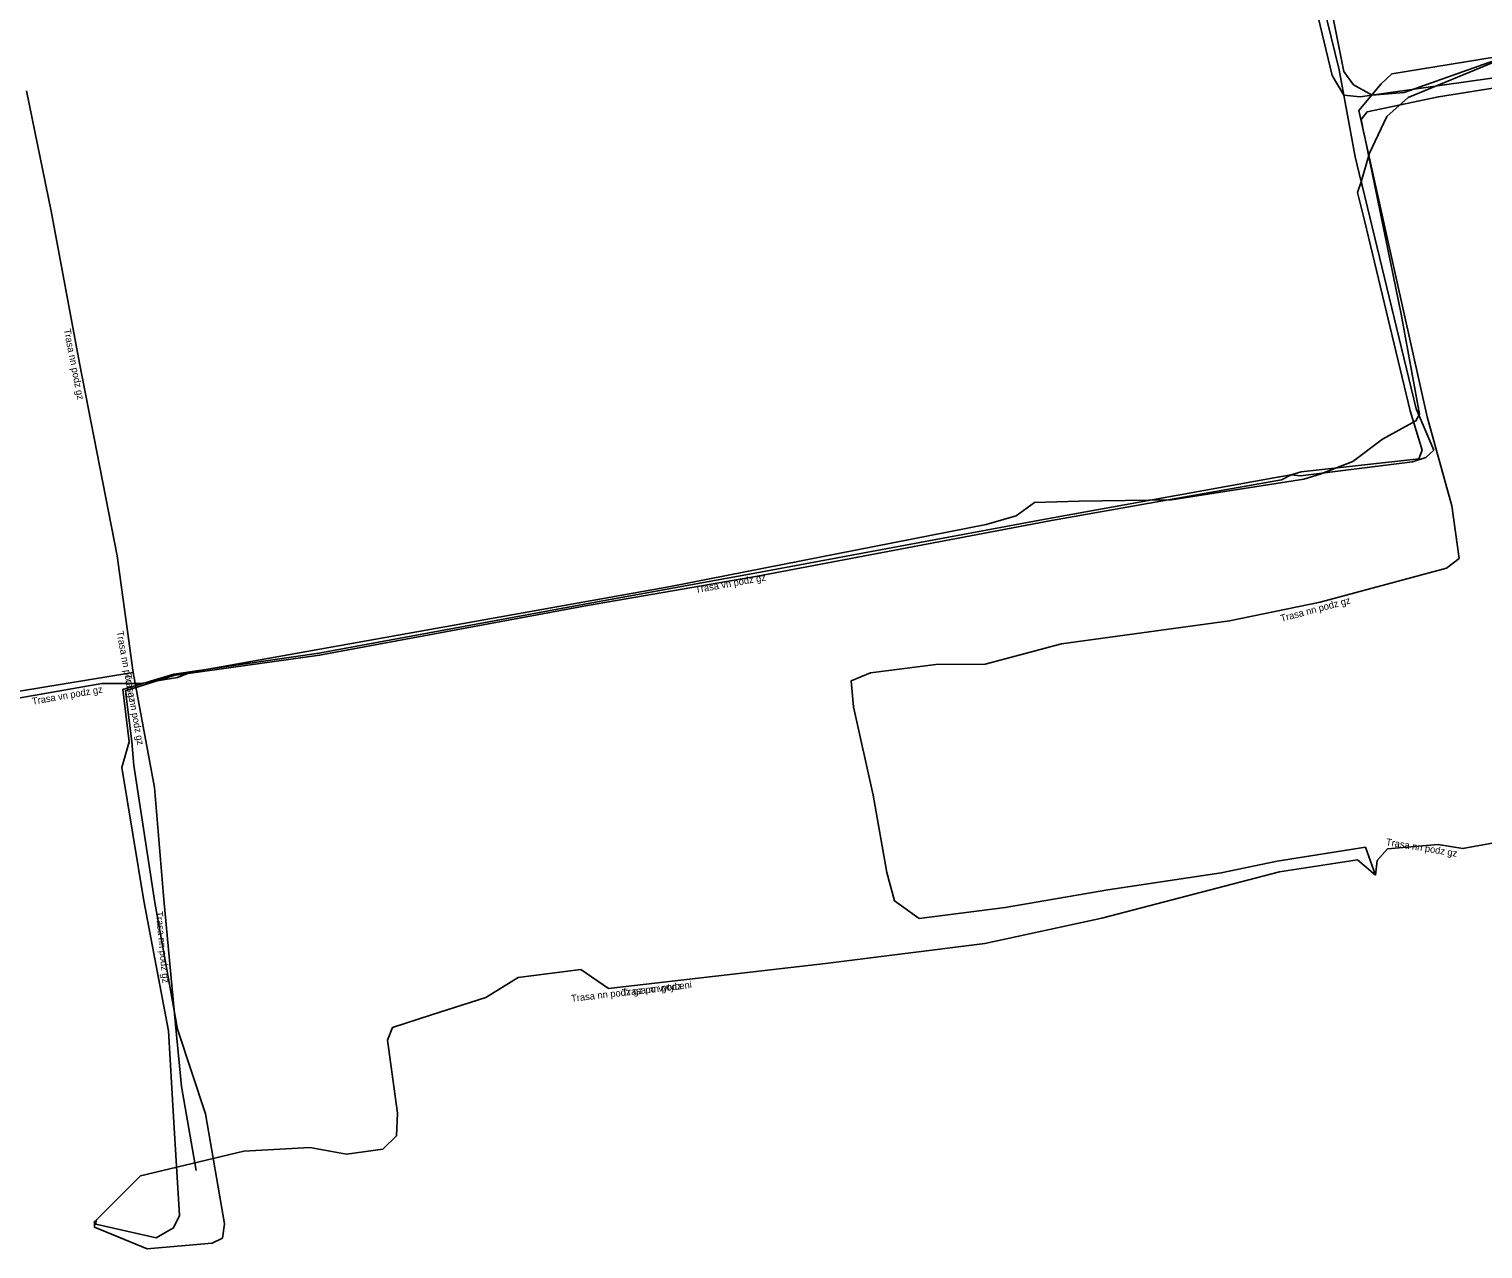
# Model space of a CAD drawing. Extents: x -473082 to -472599, y -1107914 to -1107370.
# Drawn here: x -472981 to -472876.8, y -1107720.1 to -1107632.7 of the extents above; entities that cross this region are included whole.
import ezdxf

# ---------------------------------------------------------------- set-up
doc = ezdxf.new("R2010")
doc.units = 0
for name, color, linetype in [('Popiskový text - Ostatní atributy Trasy', 7, 'Continuous'), ('Spojnice NN', 7, 'Continuous'), ('Spojnice VN', 7, 'Continuous')]:
    doc.layers.add(name, color=color, linetype=linetype)

msp = doc.modelspace()

# ---------------------------------------------------------------- linework, layer by layer
at = {"layer": 'Spojnice NN'}
for points in [[(-472875.97, -1107634.7), (-472883.29, -1107635.91), (-472884.07, -1107636.61), (-472885.67, -1107638.54), (-472883.02, -1107650.42), (-472880.76, -1107660.48), (-472879, -1107666.86), (-472878.47, -1107670.62), (-472879.39, -1107671.32), (-472888.44, -1107673.75), (-472894.93, -1107675.1), (-472906.98, -1107676.74), (-472912.44, -1107678.19), (-472915.97, -1107678.23), (-472920.65, -1107678.82), (-472922.05, -1107679.39), (-472921.88, -1107681.26), (-472920.47, -1107687.59), (-472919.49, -1107693.13), (-472918.93, -1107695.15), (-472917.16, -1107696.42), (-472911, -1107695.63), (-472903.64, -1107694.35), (-472895.52, -1107693.15), (-472891.51, -1107692.3), (-472885.2, -1107691.31), (-472884.48, -1107693.31)], [(-472981.13, -1107637.11), (-472979.37, -1107645.75), (-472977.34, -1107656.62), (-472974.63, -1107670.44), (-472973.49, -1107678.79)], [(-472997.51, -1107676.91), (-472996.73, -1107681.91), (-472995.7, -1107682.72), (-472990.89, -1107681.76), (-472981.63, -1107680.12), (-472973.49, -1107678.79)], [(-472973.49, -1107678.79), (-472973.2, -1107680.34)], [(-472973.2, -1107680.34), (-472972.35, -1107684.97)], [(-472972.35, -1107684.97), (-472971.97, -1107687.02), (-472971.3, -1107695.06), (-472970.46, -1107704), (-472970.02, -1107708.44), (-472968.98, -1107714.47)], [(-472873.9, -1107690.6), (-472878.21, -1107691.41), (-472879.98, -1107691.12), (-472883.62, -1107691.43), (-472884.35, -1107692.25), (-472884.48, -1107693.31)], [(-472884.48, -1107693.31), (-472885.77, -1107692.21), (-472891.34, -1107693.08), (-472904.07, -1107696.4), (-472912.47, -1107698.21), (-472923.89, -1107699.63), (-472939.43, -1107701.43), (-472941.42, -1107700.06), (-472945.91, -1107700.65), (-472948.22, -1107702.07), (-472952.11, -1107703.31), (-472954.9, -1107704.22), (-472955.27, -1107705.14), (-472954.55, -1107710.36), (-472954.62, -1107711.99), (-472955.6, -1107712.94), (-472958.21, -1107713.29), (-472960.83, -1107712.83), (-472965.57, -1107713.09), (-472972.96, -1107714.86), (-472976.14, -1107718.03)], [(-472884.48, -1107693.31), (-472885.77, -1107692.21), (-472891.34, -1107693.08), (-472904.07, -1107696.4), (-472912.47, -1107698.21), (-472923.89, -1107699.63), (-472939.43, -1107701.43), (-472941.42, -1107700.06), (-472945.91, -1107700.65), (-472948.22, -1107702.07), (-472952.11, -1107703.31), (-472954.9, -1107704.22), (-472955.27, -1107705.14), (-472954.55, -1107710.36), (-472954.62, -1107711.99), (-472955.6, -1107712.94), (-472958.21, -1107713.29), (-472960.83, -1107712.83), (-472965.57, -1107713.09), (-472972.96, -1107714.86), (-472976.14, -1107718.03)]]:
    msp.add_lwpolyline(points, dxfattribs=at)
at = {"layer": 'Spojnice VN'}
for points in [[(-472875.95, -1107634.94), (-472882.42, -1107637.24), (-472884.7, -1107637.44), (-472886.06, -1107636.68), (-472886.73, -1107635.73), (-472888.17, -1107628.55), (-472889.42, -1107623.23), (-472890.17, -1107619.72), (-472891.75, -1107613.81), (-472894.87, -1107599.99), (-472897.4, -1107589.9), (-472899.37, -1107581.45), (-472900.86, -1107575.05), (-472901.22, -1107573.68), (-472903.13, -1107567.52), (-472905.32, -1107556.79), (-472907.67, -1107546.67)], [(-472872.74, -1107635.74), (-472879.7, -1107636.72), (-472885.57, -1107637.54), (-472886.75, -1107637.43), (-472887.57, -1107636.03), (-472890.88, -1107622.26), (-472896.66, -1107598.66), (-472901.17, -1107578.99), (-472901.72, -1107578.58), (-472904.16, -1107579.08), (-472907.72, -1107579.66), (-472913.35, -1107580.97), (-472931.82, -1107585.01), (-472935.78, -1107585.94), (-472940.39, -1107586.9), (-472941.18, -1107586.07), (-472941.89, -1107582.19), (-472945.77, -1107566.21), (-472946.59, -1107566.01), (-472951.81, -1107566.48), (-472951.81, -1107566.06), (-472951.68, -1107565.97)], [(-472976.14, -1107718.03), (-472976.14, -1107718.13), (-472976.18, -1107718.13), (-472976.18, -1107718.32), (-472971.84, -1107719.3), (-472970.6, -1107718.58), (-472970.17, -1107717.68), (-472970.6, -1107710.63), (-472970.95, -1107704.47), (-472972.74, -1107695.15), (-472974.3, -1107685.59), (-472973.78, -1107683.75), (-472974.24, -1107680.02), (-472970.59, -1107678.9), (-472960.18, -1107677.41), (-472941, -1107673.87), (-472928.43, -1107671.59), (-472907.88, -1107667.77), (-472891.34, -1107664.78), (-472890.52, -1107664.63), (-472889.85, -1107664.7), (-472881.81, -1107663.71), (-472880.87, -1107663.4), (-472880.3, -1107662.87), (-472881.55, -1107659.9), (-472885.4, -1107644), (-472885.49, -1107643.64), (-472885.94, -1107641.84), (-472887.07, -1107635.61), (-472888.78, -1107628.66)], [(-472976.14, -1107718.03), (-472976.16, -1107718.11), (-472976.27, -1107718.11), (-472976.27, -1107718.52), (-472972.5, -1107720.08), (-472971.97, -1107720.03), (-472967.84, -1107719.68), (-472967.1, -1107719.31), (-472966.94, -1107718.3), (-472968.32, -1107710.41), (-472970.31, -1107704.35), (-472971.95, -1107695.28), (-472973.44, -1107685.46), (-472973.6, -1107683.75), (-472974.05, -1107680.11), (-472970.57, -1107679.01), (-472960.14, -1107677.56), (-472940.94, -1107674), (-472928.76, -1107671.88), (-472907.7, -1107667.9), (-472891.21, -1107664.99), (-472890.52, -1107664.63), (-472889.81, -1107664.42), (-472881.37, -1107663.49), (-472881.12, -1107662.87), (-472881.98, -1107660.05), (-472885.27, -1107646.42), (-472885.75, -1107644.4), (-472885.49, -1107643.64), (-472884.91, -1107641.59), (-472883.65, -1107638.96), (-472882.14, -1107637.59), (-472875.46, -1107634.86)], [(-472885.28, -1107640.28), (-472885.49, -1107639.17), (-472885.07, -1107638.63), (-472879.96, -1107637.54), (-472859.98, -1107634.38)], [(-472885.28, -1107640.28), (-472885.27, -1107640.33), (-472882.64, -1107653.13), (-472881.31, -1107660.28), (-472881.57, -1107660.77), (-472883.97, -1107662.08), (-472886.1, -1107663.68), (-472888.44, -1107664.58), (-472889.6, -1107664.93), (-472899.08, -1107666.41), (-472905.7, -1107666.52), (-472908.91, -1107666.61), (-472910.21, -1107667.56), (-472912.36, -1107668.19), (-472935, -1107672.62), (-472969.33, -1107678.77), (-472970.32, -1107679.14), (-472972.94, -1107679.57), (-472975.73, -1107679.57), (-472981.58, -1107680.6)]]:
    msp.add_lwpolyline(points, dxfattribs=at)

# ---------------------------------------------------------------- texts
at = {"layer": 'Popiskový text - Ostatní atributy Trasy'}
for s, rotation, p in [('Trasa nn podz gz', 281.0945, (-472978.47, -1107654.22)), ('Trasa vn podz gz', 10.2808, (-472933.17, -1107673.11)), ('Trasa nn podz gz', 15.0299, (-472891.21, -1107675.17)), ('Trasa nn podz gz', 280.4648, (-472974.69, -1107675.86)), ('Trasa nn podz gz', 280.464, (-472974.12, -1107678.94)), ('Trasa vn podz gz', 9.9856, (-472980.7, -1107681.11)), ('Trasa nn podz gz', 350.6952, (-472883.75, -1107691.16)), ('Trasa nn podz gz', 275.3677, (-472971.87, -1107695.92)), ('Trasa nn podz gz po vytyceni', 6.6071, (-472942.08, -1107702.39)), ('Trasa nn podz', 6.6071, (-472938.42, -1107701.97))]:
    msp.add_text(s, height=0.5, rotation=rotation, dxfattribs=at).set_placement(p)

doc.saveas('drawing.dxf')
